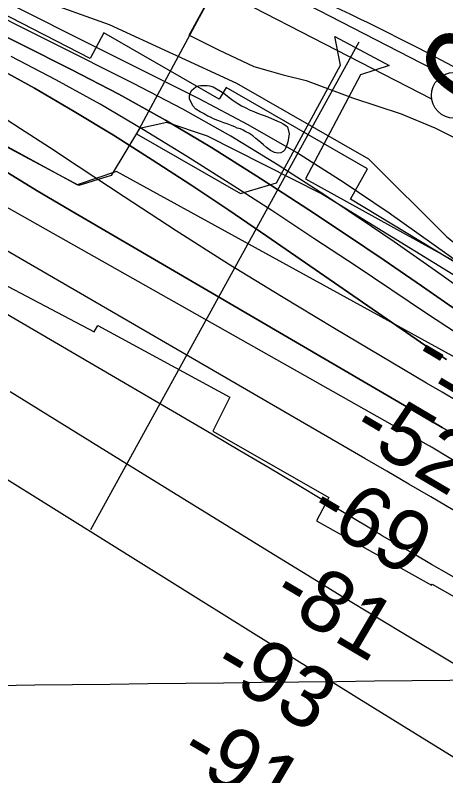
# Model space of a CAD drawing. Extents: x 3677843 to 3715951, y 511991 to 537744.
# Drawn here: x 3698067 to 3698538, y 529609 to 530440 of the extents above; entities that cross this region are included whole.
import ezdxf

# ---------------------------------------------------------------- set-up
doc = ezdxf.new("R2010")
doc.units = 0
for name, color, linetype in [('V-CHAN-DOCK', 7, 'Continuous'), ('V-GRID-MAJR', 7, 'Continuous'), ('V-LEVE-TOET', 7, 'Continuous'), ('V-RAIL-TRAK', 7, 'Continuous'), ('V-RIVR-EDGE', 7, 'Continuous'), ('V-RIVR-RANG', 7, 'Continuous'), ('V-RRAP-FSHR', 7, 'Continuous'), ('V-RRAP-RVMT', 7, 'Continuous'), ('V-SITE-VEGE', 7, 'Continuous'), ('V-SURV-IDEN', 7, 'Continuous'), ('V-SURV-LINE', 7, 'Continuous'), ('V-TOPO-DPTH', 7, 'Continuous'), ('V-TOPO-MAJR', 7, 'Continuous'), ('V-TOPO-MINR', 7, 'Continuous'), ('V-TOPO-WATR', 7, 'Continuous')]:
    doc.layers.add(name, color=color, linetype=linetype)

msp = doc.modelspace()

# ---------------------------------------------------------------- linework, layer by layer
at = {"layer": 'V-CHAN-DOCK'}
for points in [[(3699141.883, 529740.1190000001), (3698178.119, 530269.076), (3698135.037, 530254.544), (3697006.262, 530870.822)], [(3698290.741, 530479.728), (3698199.949, 530310.469), (3698313.498, 530244.982), (3698352.662, 530256.719), (3698422.63, 530385.368), (3698416.486, 530416.7), (3698475.775, 530384.795), (3698444.443, 530374.733), (3698384.551, 530261.183), (3698584.24, 530150.915)]]:
    msp.add_lwpolyline(points, dxfattribs=at)
at = {"layer": 'V-GRID-MAJR'}
msp.add_spline([(3681966.5640000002, 529526.479), (3687244.413, 529585.207), (3692522.254, 529644.703), (3697800.0870000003, 529704.966), (3703077.91, 529765.996), (3708355.725, 529827.795), (3713633.5300000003, 529890.361), (3713633.531, 529890.361)], degree=3, dxfattribs=at)
at = {"layer": 'V-LEVE-TOET'}
for points in [[(3698257.27, 530418.167), (3698290.741, 530479.728), (3696917.413, 531223.297), (3696914.169, 531217.208), (3696889.284, 531175.513)], [(3698257.27, 530418.167), (3698289.285, 530401.908), (3698327.992, 530383.736), (3698344.718, 530378.952), (3698360.008, 530374.645), (3698385.338, 530368.425), (3698435.991, 530349.772), (3698489.034, 530332.073), (3698525.8310000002, 530316.768), (3698596.073, 530281.383), (3698648.1580000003, 530253.17), (3698717.923, 530216.349), (3698793.42, 530171.403), (3698910.967, 530101.591), (3699017.0500000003, 530043.256), (3699108.792, 529985.879), (3699191.934, 529933.282)]]:
    msp.add_lwpolyline(points, dxfattribs=at)
at = {"layer": 'V-RAIL-TRAK'}
msp.add_lwpolyline([(3698763.511, 530263.363), (3698727.419, 530283.982), (3698691.215, 530304.4), (3698654.896, 530324.616), (3698618.468, 530344.629), (3698581.927, 530364.437), (3698545.278, 530384.0430000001), (3698508.525, 530403.444), (3698489.896, 530413.075), (3698471.1780000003, 530422.527), (3698452.365, 530431.792), (3698444.949, 530435.356), (3698433.464, 530440.875), (3698414.473, 530449.769), (3698395.395, 530458.48), (3698376.234, 530467.001), (3698356.989, 530475.335), (3698337.664, 530483.48), (3698318.2600000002, 530491.434), (3698298.779, 530499.198), (3698228.549, 530527.974), (3698111.659, 530585.99), (3698096.654, 530593.947), (3697969.3170000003, 530661.457)], dxfattribs=at)
at = {"layer": 'V-RIVR-EDGE'}
msp.add_lwpolyline([(3699212.039990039, 529785.429534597), (3699131.1181131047, 529834.8564150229), (3699043.5600262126, 529871.0925189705), (3698954.246987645, 529925.9430880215), (3698831.9236082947, 529983.8769153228), (3698739.608954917, 530038.7349065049), (3698601.1406859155, 530122.5227006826), (3698402.134801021, 530244.8810914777), (3698277.422005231, 530307.6234401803), (3698233.035216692, 530322.7413617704), (3698203.0027399, 530316.2120304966), (3698172.258608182, 530264.659961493), (3698136.812833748, 530253.9417293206), (3697741.7195509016, 530465.0330029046)], dxfattribs=at)
at = {"layer": 'V-RIVR-RANG'}
msp.add_line((3698442.8233, 530410.4981), (3698149.5407, 529877.9107), dxfattribs=at)
at = {"layer": 'V-RRAP-FSHR'}
msp.add_lwpolyline([(3697923.104166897, 530518.0682014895), (3698170.086823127, 530429.7236254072), (3698308.943271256, 530365.6744733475), (3698453.491111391, 530282.8492572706), (3698539.0893194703, 530197.879785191), (3698677.241255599, 530087.6502810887), (3698911.5959438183, 529952.3573529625), (3699042.327975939, 529875.5102488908), (3699175.921064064, 529784.7777048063), (3699418.297768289, 529632.0091926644), (3699522.3095443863, 529572.7544086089), (3699644.4522645, 529530.1662485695), (3699682.6228885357, 529522.7586325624), (3699809.3572246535, 529454.0625684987), (3699891.856808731, 529369.3306644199), (3700284.892585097, 529117.410280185), (3700663.3179294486, 528890.0884239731), (3701052.308905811, 528660.5813517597), (3701560.591786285, 528323.0258954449), (3702060.24029875, 527983.0763271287), (3702175.2764588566, 527854.2796550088), (3702403.052971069, 527666.5784068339), (3702736.6783153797, 527465.5917826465), (3703307.257259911, 527130.3218943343)], dxfattribs=at)
at = {"layer": 'V-RRAP-RVMT'}
for points in [[(3699411.3930000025, 529629.4220000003), (3699027.0450000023, 529846.9100000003), (3699038.1700000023, 529869.0740000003), (3698919.1690000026, 529935.2800000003), (3698917.4160000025, 529931.8640000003), (3698788.9680000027, 530000.6140000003), (3698788.1270000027, 529998.8850000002), (3698546.8950000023, 530150.8850000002), (3698555.3170000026, 530165.4470000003), (3698433.7190000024, 530238.8330000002), (3698452.0710000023, 530272.1010000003), (3698297.8920000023, 530360.7950000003), (3698290.2390000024, 530348.0050000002), (3698164.1420000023, 530420.6840000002), (3698149.096000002, 530392.6180000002), (3697825.1680000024, 530559.2330000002)], [(3698032.2470000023, 530157.7380000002), (3698153.4170000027, 530094.0200000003), (3698157.6640000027, 530100.7950000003), (3698301.6990000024, 530022.7260000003), (3698283.1520000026, 529985.4010000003), (3698410.0490000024, 529912.9230000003), (3698396.4850000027, 529887.6570000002), (3698522.1510000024, 529817.1760000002), (3698522.7920000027, 529818.2480000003), (3698653.2480000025, 529744.4170000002), (3698652.4790000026, 529742.6460000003), (3698776.2310000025, 529671.5620000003), (3698778.8960000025, 529676.1780000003), (3698897.8530000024, 529611.3580000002), (3698884.4180000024, 529585.8210000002), (3699018.2710000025, 529514.9080000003), (3699020.1230000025, 529518.1660000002), (3699140.2540000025, 529451.5770000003), (3699139.7850000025, 529449.8200000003), (3699263.5930000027, 529379.4790000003)]]:
    msp.add_lwpolyline(points, dxfattribs=at)
at = {"layer": 'V-SITE-VEGE'}
msp.add_lwpolyline([(3698264.514, 530337.088), (3698261.188, 530340.892), (3698259.287, 530345.643), (3698257.864, 530348.0210000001), (3698257.864, 530351.822), (3698258.816, 530355.623), (3698260.242, 530357.9990000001), (3698262.144, 530359.424), (3698264.522, 530361.802), (3698267.846, 530362.748), (3698270.224, 530363.223), (3698276.876, 530363.221), (3698279.727, 530362.746), (3698283.528, 530361.794), (3698295.406, 530354.662), (3698299.207, 530351.334), (3698302.531, 530348.957), (3698305.384, 530346.581), (3698314.409, 530340.875), (3698318.686, 530338.975), (3698323.912, 530336.122), (3698328.186, 530334.694), (3698331.989, 530332.792), (3698343.395, 530328.987), (3698353.848, 530324.231), (3698357.649, 530322.806), (3698360.022, 530321.378), (3698362.873, 530319.478), (3698364.774, 530318.05), (3698366.6720000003, 530310.448), (3698365.72, 530303.319), (3698364.77, 530299.993), (3698363.342, 530296.192), (3698361.917, 530292.866), (3698360.014, 530290.965), (3698357.639, 530289.542), (3698354.313, 530289.069), (3698350.509, 530290.019), (3698346.233, 530291.922), (3698341.957, 530295.248), (3698338.633, 530298.101), (3698335.782, 530300.954), (3698330.0810000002, 530305.232), (3698326.755, 530308.083), (3698322.481, 530310.936), (3698319.1550000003, 530312.363), (3698316.304, 530314.264), (3698313.453, 530315.691), (3698309.6520000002, 530316.6410000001), (3698307.274, 530318.069), (3698304.423, 530319.019), (3698298.724, 530321.397), (3698295.398, 530322.349), (3698291.597, 530323.774), (3698288.7460000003, 530324.727), (3698283.992, 530326.629), (3698280.667, 530328.53), (3698277.816, 530329.482), (3698273.0640000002, 530332.333), (3698269.261, 530334.236)], close=True, dxfattribs=at)
at = {"layer": 'V-SURV-LINE'}
for points in [[(3698211.8497458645, 530541.9935085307), (3698536.179143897, 530374.811929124)], [(3698522.4263614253, 530348.1499516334), (3698198.097768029, 530515.3311162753)]]:
    msp.add_lwpolyline(points, dxfattribs=at)
msp.add_circle((3698547.0687, 530352.3229499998), 25, dxfattribs=at)
at = {"layer": 'V-TOPO-DPTH'}
for points in [[(3699642.452873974, 529508.9735581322), (3698859.1102816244, 529978.8356877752), (3698818.342476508, 530003.1999682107), (3698777.5228303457, 530027.4767622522), (3698736.6254226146, 530051.6223267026), (3698695.676173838, 530075.6804047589), (3698627.978791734, 530115.3071656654), (3698620.924430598, 530119.613037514), (3698613.9831510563, 530124.0874327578), (3698607.211493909, 530128.8146130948), (3698600.5529183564, 530133.7103168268), (3698594.369001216, 530138.4351516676), (3698584.6658880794, 530145.7689585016), (3698574.912577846, 530153.034642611), (3698565.083971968, 530160.1981426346), (3698555.205168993, 530167.2935199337), (3698475.962935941, 530223.5841575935), (3698425.7031683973, 530257.5713897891), (3698374.4851954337, 530289.963327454), (3698321.829914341, 530319.9623233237), (3698268.216427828, 530348.3660246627), (3696666.362582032, 531150.28066046)], [(3699254.3535360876, 529704.0727774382), (3699122.52736756, 529781.7824036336), (3698990.322875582, 529858.8466431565), (3698857.866167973, 529935.480624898), (3698642.7695027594, 530059.2258919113), (3698617.861548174, 530073.9649736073), (3698593.206032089, 530089.1040909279), (3698568.9291737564, 530104.8432616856), (3698544.9047539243, 530120.9824680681), (3698511.126150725, 530144.2806629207), (3698470.285265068, 530172.1949018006), (3698429.2887295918, 530199.8765000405), (3698388.058719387, 530227.20913732), (3698346.6730593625, 530254.3091339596), (3698331.4056230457, 530264.2141754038), (3698281.7912397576, 530295.2586168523), (3698231.5407757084, 530325.1943966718), (3698180.3361905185, 530353.4671840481), (3698128.495524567, 530380.6313097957), (3696875.453115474, 531011.2504288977)], [(3696875.453115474, 531011.2504288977), (3698128.495524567, 530380.6313097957), (3698180.3361905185, 530353.4671840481), (3698231.5407757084, 530325.1943966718), (3698281.7912397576, 530295.2586168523), (3698331.4056230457, 530264.2141754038), (3698346.6730593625, 530254.3091339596), (3698388.058719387, 530227.20913732), (3698429.2887295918, 530199.8765000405), (3698470.285265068, 530172.1949018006), (3698511.126150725, 530144.2806629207), (3698544.9047539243, 530120.9824680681), (3698568.9291737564, 530104.8432616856), (3698593.206032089, 530089.1040909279), (3698617.861548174, 530073.9649736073), (3698642.7695027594, 530059.2258919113), (3698857.866167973, 529935.480624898), (3698990.322875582, 529858.8466431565), (3699122.52736756, 529781.7824036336), (3699254.3535360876, 529704.0727774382)], [(3698044.2716721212, 530384.0732519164), (3698088.289462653, 530360.0302466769), (3698131.650057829, 530334.8213044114), (3698174.5725227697, 530308.8350707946), (3698216.9718501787, 530281.9695771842), (3698259.112632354, 530254.7104908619), (3698300.86559668, 530226.861015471), (3698342.360015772, 530198.6179473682), (3698510.207429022, 530082.636169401), (3698519.597994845, 530076.2728165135), (3698529.0633172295, 530070.0249912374), (3698538.6407744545, 530063.9504573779)], [(3698044.2716721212, 530384.0732519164), (3698088.289462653, 530360.0302466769), (3698131.650057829, 530334.8213044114), (3698174.5725227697, 530308.8350707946), (3698216.9718501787, 530281.9695771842), (3698259.112632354, 530254.7104908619), (3698300.86559668, 530226.861015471), (3698342.360015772, 530198.6179473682), (3698510.207429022, 530082.636169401), (3698519.597994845, 530076.2728165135), (3698529.0633172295, 530070.0249912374), (3698538.6407744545, 530063.9504573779)], [(3699629.4357608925, 529410.5632713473), (3699121.094159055, 529691.8382899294), (3699025.4682609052, 529745.1445856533), (3698930.069504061, 529798.8513892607), (3698835.011459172, 529853.1589546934), (3698740.1805555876, 529907.8670280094), (3698585.08898925, 529997.9927799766), (3698567.9858959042, 530007.9582649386), (3698550.8983428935, 530017.9502549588), (3698533.8341003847, 530027.9820025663), (3698516.78539821, 530038.0402552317), (3698416.25699915, 530097.5070430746), (3698358.1749611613, 530132.4636886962), (3698300.4574984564, 530168.0024732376), (3698243.286898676, 530204.4144661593), (3698186.480874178, 530241.4085980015), (3698136.201577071, 530274.6992646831), (3698104.726030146, 530295.3561692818), (3698073.1401684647, 530315.841457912), (3698041.388834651, 530336.0693225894)], [(3699629.4357608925, 529410.5632713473), (3699121.094159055, 529691.8382899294), (3699025.4682609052, 529745.1445856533), (3698930.069504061, 529798.8513892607), (3698835.011459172, 529853.1589546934), (3698740.1805555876, 529907.8670280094), (3698585.08898925, 529997.9927799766), (3698567.9858959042, 530007.9582649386), (3698550.8983428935, 530017.9502549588), (3698533.8341003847, 530027.9820025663), (3698516.78539821, 530038.0402552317), (3698416.25699915, 530097.5070430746), (3698358.1749611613, 530132.4636886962), (3698300.4574984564, 530168.0024732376), (3698243.286898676, 530204.4144661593), (3698186.480874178, 530241.4085980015), (3698136.201577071, 530274.6992646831), (3698104.726030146, 530295.3561692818), (3698073.1401684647, 530315.841457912), (3698041.388834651, 530336.0693225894)], [(3698049.95499322, 530273.0732222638), (3698091.2715403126, 530248.0995654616), (3698132.814814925, 530223.4953648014), (3698510.315593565, 530003.3392440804), (3698522.1555550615, 529996.4184147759), (3698533.9862749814, 529989.481859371), (3698545.8031325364, 529982.5217148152), (3698557.6107485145, 529975.5458441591), (3699123.990674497, 529640.1692564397), (3699208.940766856, 529590.0096626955), (3699293.9737536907, 529539.9913952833), (3699379.1310822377, 529490.1851173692), (3699464.3713052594, 529440.5201657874), (3699604.1534663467, 529359.3095750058), (3699619.5639082, 529350.3544146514), (3699634.973186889, 529341.397253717), (3699650.3807208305, 529332.4370919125), (3699665.7870916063, 529323.4749295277), (3700087.8842460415, 529077.8784242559), (3700189.323865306, 529018.164377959)], [(3698049.95499322, 530273.0732222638), (3698091.2715403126, 530248.0995654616), (3698132.814814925, 530223.4953648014), (3698510.315593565, 530003.3392440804), (3698522.1555550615, 529996.4184147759), (3698533.9862749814, 529989.481859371), (3698545.8031325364, 529982.5217148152), (3698557.6107485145, 529975.5458441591), (3699123.990674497, 529640.1692564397), (3699208.940766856, 529590.0096626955), (3699293.9737536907, 529539.9913952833), (3699379.1310822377, 529490.1851173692), (3699464.3713052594, 529440.5201657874), (3699604.1534663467, 529359.3095750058), (3699619.5639082, 529350.3544146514), (3699634.973186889, 529341.397253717), (3699650.3807208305, 529332.4370919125), (3699665.7870916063, 529323.4749295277), (3700087.8842460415, 529077.8784242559), (3700189.323865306, 529018.164377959)]]:
    msp.add_lwpolyline(points, dxfattribs=at)
at = {"layer": 'V-TOPO-MAJR'}
msp.add_lwpolyline([(3700625.5395838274, 528706.5258531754), (3699822.438437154, 529174.8288823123), (3699786.8468077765, 529195.694994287), (3699751.321016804, 529216.6720126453), (3699715.8939834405, 529237.815390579), (3699680.5327884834, 529259.0696748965), (3699619.5538211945, 529295.9167424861), (3699614.7355021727, 529298.8372470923), (3699609.922531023, 529301.7665116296), (3699605.1175816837, 529304.7089160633), (3699600.3179802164, 529307.6600804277), (3699138.3252467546, 529592.5992999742), (3699035.783043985, 529655.6722460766), (3698933.139571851, 529718.5795051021), (3698830.3441956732, 529781.2382335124), (3698727.44755013, 529843.7312748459), (3698524.0182786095, 529966.9449695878), (3698522.7568651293, 529967.7009950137), (3698521.4908517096, 529968.4491532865), (3698520.2179383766, 529969.1855108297), (3698518.9404251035, 529969.91400122), (3697830.2534854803, 530358.4007440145)], dxfattribs=at)
at = {"layer": 'V-TOPO-MINR'}
for points in [[(3699647.544549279, 529487.3495660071), (3699132.699767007, 529795.446868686), (3699044.8032540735, 529847.8040268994), (3698956.765868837, 529899.92211691), (3698868.5171751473, 529951.6816046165), (3698780.127609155, 530003.2020241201), (3698635.3375627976, 530087.2029628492), (3698619.385465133, 530096.7724128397), (3698603.630447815, 530106.6463361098), (3698588.171051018, 530116.9769692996), (3698572.9087345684, 530127.6120757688), (3698554.641771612, 530140.7421488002), (3698530.3151770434, 530158.0576811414), (3698505.8834032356, 530175.222018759), (3698481.293860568, 530192.1595642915), (3698456.599138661, 530208.9459151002), (3698405.578475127, 530243.2834080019), (3698354.7100070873, 530276.1246578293), (3698303.0648104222, 530307.6364931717), (3698250.2545208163, 530337.1542067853), (3698196.667502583, 530365.3425059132), (3696770.3815006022, 531081.1738087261)], [(3699254.3535360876, 529704.0727774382), (3699122.52736756, 529781.7824036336), (3698990.322875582, 529858.8466431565), (3698857.866167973, 529935.480624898), (3698642.7695027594, 530059.2258919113), (3698617.861548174, 530073.9649736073), (3698593.206032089, 530089.1040909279), (3698568.9291737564, 530104.8432616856), (3698544.9047539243, 530120.9824680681), (3698511.126150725, 530144.2806629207), (3698470.285265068, 530172.1949018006), (3698429.2887295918, 530199.8765000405), (3698388.058719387, 530227.20913732), (3698346.6730593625, 530254.3091339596), (3698331.4056230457, 530264.2141754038), (3698281.7912397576, 530295.2586168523), (3698231.5407757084, 530325.1943966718), (3698180.3361905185, 530353.4671840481), (3698128.495524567, 530380.6313097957), (3696875.453115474, 531011.2504288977)], [(3700189.6925895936, 528900.9640653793), (3700101.0409259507, 528955.8405440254), (3699634.6806993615, 529243.4325393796), (3699612.4988219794, 529257.0899857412), (3699590.304168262, 529270.7266047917), (3699568.0903500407, 529284.3319828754), (3699545.863755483, 529297.9165336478), (3699166.841134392, 529529.2032125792), (3699055.8221463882, 529596.5786874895), (3698944.586503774, 529663.5925507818), (3698833.025879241, 529730.0639966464), (3698721.2486000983, 529796.173830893), (3698545.376105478, 529899.6151704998), (3698521.359778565, 529913.7112047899), (3698497.326391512, 529927.778030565), (3698473.2674142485, 529941.8010435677), (3698449.1913768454, 529955.7948480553), (3697514.38, 530498)], [(3699271.3840873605, 529418.6030720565), (3698796.0446141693, 529687.2828053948), (3698753.7099964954, 529711.1135253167), (3698711.319763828, 529734.8444888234), (3698668.846108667, 529758.4258177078), (3698626.3168385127, 529781.9073901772), (3698579.8615112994, 529807.4498677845), (3698560.5618136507, 529818.1622692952), (3698541.320269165, 529828.9771719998), (3698522.1659544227, 529839.9458264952), (3698503.0697928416, 529851.0169821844), (3698471.6480247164, 529869.4025212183), (3698468.3098659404, 529871.3636917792), (3698464.9763702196, 529873.3327248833), (3698461.6498690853, 529875.3135518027), (3698458.3280310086, 529877.3022412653), (3698404.2036589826, 529909.8352914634), (3698373.7896487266, 529928.0399102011), (3698343.330995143, 529946.1692074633), (3698312.805376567, 529964.185522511), (3698282.235114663, 529982.1265160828), (3697521.1090301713, 530426.9204379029)], [(3699277.703931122, 529671.9592373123), (3699174.1394559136, 529731.9804682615), (3699070.3468171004, 529791.610573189), (3698650.2667233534, 530031.368920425), (3698616.361229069, 530051.2042419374), (3698582.7505783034, 530071.5158686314), (3698549.582192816, 530092.5419530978), (3698516.708650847, 530114.044342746), (3698439.694918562, 530165.6035415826), (3698393.7014383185, 530196.1313965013), (3698347.548544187, 530226.414177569), (3698301.156529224, 530256.3293478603), (3698254.605100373, 530285.9994443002), (3698207.541864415, 530314.7934097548), (3698159.956659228, 530342.6660806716), (3698111.588500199, 530369.1568097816), (3698062.6983719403, 530394.7262443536)], [(3698538.6407744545, 530063.9504573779), (3698529.0633172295, 530070.0249912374), (3698519.597994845, 530076.2728165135), (3698510.207429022, 530082.636169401), (3698342.360015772, 530198.6179473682), (3698300.86559668, 530226.861015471), (3698259.112632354, 530254.7104908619), (3698216.9718501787, 530281.9695771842), (3698174.5725227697, 530308.8350707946), (3698131.650057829, 530334.8213044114), (3698088.289462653, 530360.0302466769), (3698044.2716721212, 530384.0732519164)], [(3699629.4357608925, 529410.5632713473), (3699121.094159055, 529691.8382899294), (3699025.4682609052, 529745.1445856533), (3698930.069504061, 529798.8513892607), (3698835.011459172, 529853.1589546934), (3698740.1805555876, 529907.8670280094), (3698585.08898925, 529997.9927799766), (3698567.9858959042, 530007.9582649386), (3698550.8983428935, 530017.9502549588), (3698533.8341003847, 530027.9820025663), (3698516.78539821, 530038.0402552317), (3698416.25699915, 530097.5070430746), (3698358.1749611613, 530132.4636886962), (3698300.4574984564, 530168.0024732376), (3698243.286898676, 530204.4144661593), (3698186.480874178, 530241.4085980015), (3698136.201577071, 530274.6992646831), (3698104.726030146, 530295.3561692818), (3698073.1401684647, 530315.841457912), (3698041.388834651, 530336.0693225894)], [(3700189.323865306, 529018.164377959), (3700087.8842460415, 529077.8784242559), (3699665.7870916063, 529323.4749295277), (3699650.3807208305, 529332.4370919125), (3699634.973186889, 529341.397253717), (3699619.5639082, 529350.3544146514), (3699604.1534663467, 529359.3095750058), (3699464.3713052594, 529440.5201657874), (3699379.1310822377, 529490.1851173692), (3699293.9737536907, 529539.9913952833), (3699208.940766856, 529590.0096626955), (3699123.990674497, 529640.1692564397), (3698557.6107485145, 529975.5458441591), (3698545.8031325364, 529982.5217148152), (3698533.9862749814, 529989.481859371), (3698522.1555550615, 529996.4184147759), (3698510.315593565, 530003.3392440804), (3698132.814814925, 530223.4953648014), (3698091.2715403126, 530248.0995654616), (3698049.95499322, 530273.0732222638)], [(3699283.8943893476, 529174.09828313), (3698442.5891394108, 529693.2729937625), (3698411.655347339, 529712.3933579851), (3698380.74005698, 529731.5435423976), (3698349.8525191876, 529750.7384570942), (3698318.983483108, 529769.9631919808), (3697561.1727498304, 530242.6769681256)], [(3700249.711041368, 528730.9817859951), (3699581.9899404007, 529116.2805903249), (3699549.272116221, 529135.1660252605), (3699516.5578086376, 529154.0575478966), (3699483.8487759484, 529172.9582020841), (3699451.143259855, 529191.8649439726), (3699418.482494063, 529210.8478600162), (3699385.8778762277, 529229.9262496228), (3699353.3574803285, 529249.1478495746), (3699320.8932323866, 529268.46492309), (3698499.341551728, 529759.7590390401), (3698461.815489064, 529782.3051430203), (3698424.3519404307, 529804.9541706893), (3698386.982162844, 529827.7575838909), (3698349.6748992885, 529850.6639207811), (3698182.430463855, 529953.8262702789), (3698061.603312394, 530028.4803651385)]]:
    msp.add_lwpolyline(points, dxfattribs=at)
at = {"layer": 'V-TOPO-WATR'}
msp.add_lwpolyline([(3699642.452873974, 529508.9735581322), (3698859.1102816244, 529978.8356877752), (3698818.342476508, 530003.1999682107), (3698777.5228303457, 530027.4767622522), (3698736.6254226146, 530051.6223267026), (3698695.676173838, 530075.6804047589), (3698627.978791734, 530115.3071656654), (3698620.924430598, 530119.613037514), (3698613.9831510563, 530124.0874327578), (3698607.211493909, 530128.8146130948), (3698600.5529183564, 530133.7103168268), (3698594.369001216, 530138.4351516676), (3698584.6658880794, 530145.7689585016), (3698574.912577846, 530153.034642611), (3698565.083971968, 530160.1981426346), (3698555.205168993, 530167.2935199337), (3698475.962935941, 530223.5841575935), (3698425.7031683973, 530257.5713897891), (3698374.4851954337, 530289.963327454), (3698321.829914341, 530319.9623233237), (3698268.216427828, 530348.3660246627), (3696666.362582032, 531150.28066046)], dxfattribs=at)

# ---------------------------------------------------------------- texts
at = {"layer": 'V-RIVR-RANG'}
for s, rotation, p in [('-18', 329.1383257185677, (3698497.9632622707, 530056.5819530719)), ('-52', 329.4263888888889, (3698431.4193924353, 529979.3658784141)), ('-69', 329.4263888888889, (3698384.6574433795, 529890.8456461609)), ('-81', 329.4263888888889, (3698344.481624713, 529798.4334804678)), ('-93', 329.4263888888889, (3698279.551040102, 529720.6458577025)), ('-91', 329.4263888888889, (3698243.235056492, 529625.9537999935))]:
    msp.add_text(s, height=66.99999999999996, rotation=rotation, dxfattribs=at).set_placement(p)
at = {"layer": 'V-SURV-IDEN'}
msp.add_text('   683+52.8   ', height=100.00000000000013, rotation=59.818611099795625, dxfattribs=at).set_placement((3698531.925443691, 530224.9090572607))

doc.saveas('drawing.dxf')
